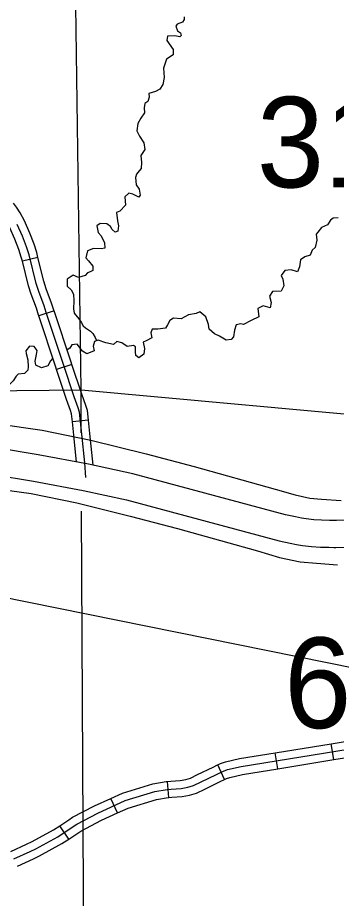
# Model space of a CAD drawing. Extents: x -492261 to -432772, y 1441225 to 1452922.
# Drawn here: x -457961.8 to -457876.9, y 1450967.5 to 1451202.4 of the extents above; entities that cross this region are included whole.
import ezdxf

# ---------------------------------------------------------------- set-up
doc = ezdxf.new("R2010")
doc.units = 0
doc.layers.add('Default', color=7, linetype='Continuous')
doc.layers.add('R_Draft', color=7, linetype='Continuous')

msp = doc.modelspace()

# ---------------------------------------------------------------- linework, layer by layer
at = {"layer": 'Default'}
for p, q in [((-457956.37, 1451138.48), (-457960.53, 1451137.45)), ((-457952.07, 1451124.21), (-457956.14, 1451122.86)), ((-457947.33, 1451109.9), (-457951.4, 1451108.54)), ((-457942.94, 1451095.03), (-457947.2, 1451094.59)), ((-457877.58, 1451004.53), (-457878.26, 1451008.76)), ((-457892.47, 1451002.12), (-457893.15, 1451006.35)), ((-457906.65, 1450999.26), (-457908.46, 1451003.15)), ((-457921.54, 1450994.44), (-457921.87, 1450998.72)), ((-457935.2, 1450990.31), (-457936.98, 1450994.2)), ((-457948.17, 1450983.34), (-457950.54, 1450986.91))]:
    msp.add_line(p, q, dxfattribs=at)
for points in [[(-457944.83, 1451091.7), (-457944.89, 1451103.15), (-457946.83, 1451244.05), (-457946.97, 1451253.15), (-457946.94, 1451394.95), (-457946.87, 1451404.85), (-457947.93, 1451544), (-457948.01, 1451552.92)], [(-457917.4, 1451202.65), (-457917.44, 1451201.93), (-457917.85, 1451201.17), (-457919.27, 1451200.65), (-457919.68, 1451200.12), (-457919.22, 1451198.87), (-457918.38, 1451198.35), (-457918.19, 1451197.61), (-457918.58, 1451197.31), (-457919.9, 1451197.59), (-457921.85, 1451197.49), (-457922.02, 1451196.28), (-457920.38, 1451193.88), (-457920.35, 1451192.48), (-457922.15, 1451191.29), (-457922.89, 1451188.92), (-457922.74, 1451186.48), (-457923.09, 1451184.61), (-457923.95, 1451183.36), (-457925.1, 1451182.7), (-457926.8, 1451182.14), (-457926.78, 1451181.16), (-457927.12, 1451180.04), (-457927.88, 1451179.47), (-457928.08, 1451178.35), (-457928.02, 1451176.98), (-457928.93, 1451175.63), (-457929.75, 1451174.18), (-457930.01, 1451172.22), (-457929.32, 1451170.78), (-457928.16, 1451169), (-457927.94, 1451167.26), (-457928.96, 1451165.66), (-457928.82, 1451163.74), (-457928.87, 1451162.19), (-457929.4, 1451161.52), (-457930.09, 1451160.67), (-457930.35, 1451159.74), (-457930.22, 1451157.82), (-457929.39, 1451156.67), (-457929.18, 1451155.1), (-457929.53, 1451154.54), (-457931.13, 1451155.36), (-457932.13, 1451155.63), (-457933.25, 1451154.62), (-457933.08, 1451152.39), (-457934.56, 1451150.83), (-457935.46, 1451150.41), (-457935.18, 1451148.24), (-457934.94, 1451146.9), (-457935.08, 1451145.49), (-457935.81, 1451145.18), (-457936.63, 1451145.91), (-457937.08, 1451146.67), (-457938.05, 1451147.45), (-457939.76, 1451147.52), (-457940.72, 1451146.87), (-457940.33, 1451145.13), (-457939.51, 1451144.2), (-457938.63, 1451142.33), (-457938.59, 1451140.93), (-457939.56, 1451140.73), (-457941.57, 1451140.8), (-457943.15, 1451140.24), (-457943.65, 1451138.31), (-457942.94, 1451137.55), (-457941.79, 1451136.09), (-457941.76, 1451135), (-457942.47, 1451134.61), (-457943.15, 1451134.33), (-457943.84, 1451133.63), (-457945.57, 1451133.1), (-457946.99, 1451133.72), (-457948.59, 1451132.68), (-457948.6, 1451130.76), (-457947.49, 1451129.84), (-457946.86, 1451128.68), (-457946.82, 1451126.9), (-457946.93, 1451124.78), (-457946.7, 1451123.61), (-457945.47, 1451122.12), (-457944.84, 1451121.22), (-457944.33, 1451120.25), (-457943.69, 1451119.7), (-457942.38, 1451118.81), (-457941.79, 1451118.14), (-457941.16, 1451117.06), (-457941.04, 1451116.84), (-457940.65, 1451116.24)], [(-457956.37, 1451138.48), (-457956.68, 1451139.73), (-457957.41, 1451141.97), (-457958.55, 1451144.91), (-457959.96, 1451148.19), (-457961.07, 1451150.34), (-457962.07, 1451151.89), (-457962.93, 1451152.97)], [(-457960.53, 1451137.45), (-457960.8, 1451138.55), (-457961.45, 1451140.53), (-457962.52, 1451143.29), (-457963.84, 1451146.36), (-457964.78, 1451148.19), (-457965.55, 1451149.38), (-457966.28, 1451150.29)], [(-457877.77, 1451148.92), (-457878.47, 1451148.41), (-457879.27, 1451147.13), (-457880.85, 1451146.4), (-457881.85, 1451145.18), (-457882.24, 1451144.68), (-457882.11, 1451143.08), (-457882.55, 1451141.09), (-457883.33, 1451140.35), (-457883.87, 1451139.05), (-457885.29, 1451138.61), (-457886.41, 1451137.78), (-457886.73, 1451135.96), (-457887.27, 1451134.63), (-457888.95, 1451135.19), (-457890.63, 1451134.95), (-457891.6, 1451133.66), (-457891.14, 1451132.67), (-457890.9, 1451130.9), (-457891.6, 1451129.42), (-457893.86, 1451129.34), (-457894.66, 1451128.17), (-457894.27, 1451126.4), (-457894.52, 1451125.05), (-457896.36, 1451125.52), (-457897.78, 1451124.88), (-457897.58, 1451122.59), (-457899.58, 1451121.62), (-457901.61, 1451120.57), (-457902.36, 1451120.72), (-457903.56, 1451120.49), (-457903.98, 1451119.02), (-457904.28, 1451117.32), (-457904.92, 1451116.59), (-457906.28, 1451116.35), (-457908, 1451117.49), (-457909.36, 1451118.08), (-457910.76, 1451119.31), (-457910.97, 1451120.57), (-457911.62, 1451122.59), (-457913.25, 1451123.95), (-457914.27, 1451123.49), (-457916.24, 1451123.13), (-457917.22, 1451122.62), (-457918.18, 1451122.08), (-457920.24, 1451122.23), (-457921.26, 1451121.63), (-457921.83, 1451120.5), (-457922.38, 1451119.57), (-457924.43, 1451119.29), (-457925.95, 1451119.33), (-457926.27, 1451118.32), (-457926.06, 1451117.04), (-457927.56, 1451116.2), (-457928.38, 1451115.89), (-457927.99, 1451114.15), (-457928.18, 1451112.65), (-457929.5, 1451111.68), (-457930.32, 1451112.31), (-457930.37, 1451113.32), (-457930.35, 1451114.64), (-457930.9, 1451114.94), (-457932.58, 1451114.7), (-457934.03, 1451115.72), (-457935.33, 1451116), (-457936.25, 1451115.26), (-457938.27, 1451115.67), (-457940.31, 1451116.37), (-457941.31, 1451116), (-457941.67, 1451114.76), (-457941.44, 1451113.53), (-457943.34, 1451112.79), (-457944.53, 1451113.48), (-457945.95, 1451115.31), (-457947.38, 1451115.15), (-457947.87, 1451114.23), (-457948.62, 1451113.8)], [(-457876.37, 1451149.04), (-457877.77, 1451148.92)], [(-457943.58, 1451079.8), (-457943.89, 1451083.65), (-457944.71, 1451091.31), (-457945.32, 1451097.17), (-457945.66, 1451098.31), (-457946.71, 1451101.27), (-457949.59, 1451109.89), (-457954.17, 1451123.74), (-457954.76, 1451125.59), (-457956.17, 1451129.39), (-457956.86, 1451131.5), (-457958.74, 1451139.14), (-457959.43, 1451141.25), (-457960.53, 1451144.1), (-457961.9, 1451147.27)], [(-457956.14, 1451122.86), (-457956.21, 1451123.07), (-457956.79, 1451124.89), (-457958.2, 1451128.69), (-457958.92, 1451130.91), (-457960.53, 1451137.45)], [(-457952.07, 1451124.21), (-457952.13, 1451124.4), (-457952.74, 1451126.29), (-457954.15, 1451130.1), (-457954.8, 1451132.09), (-457956.37, 1451138.48)], [(-457951.4, 1451108.54), (-457951.62, 1451109.21), (-457956.14, 1451122.86)], [(-457947.33, 1451109.9), (-457947.55, 1451110.56), (-457952.07, 1451124.21)], [(-457952.42, 1451111.63), (-457953.01, 1451110.91), (-457953.75, 1451109.51), (-457955.42, 1451109.04), (-457956.93, 1451109.69), (-457957.1, 1451110.77), (-457956.77, 1451112.53), (-457956.6, 1451113.62), (-457957.34, 1451114.72), (-457958.66, 1451114.78), (-457959.6, 1451113.55), (-457959.52, 1451112.81), (-457959.05, 1451111.18), (-457958.95, 1451109.32), (-457959.07, 1451108.43), (-457959.99, 1451107.52), (-457961.67, 1451107.3), (-457962.14, 1451106.83), (-457963, 1451105.58), (-457964.19, 1451104.29), (-457965.6, 1451103.72)], [(-457947.2, 1451094.59), (-457947.43, 1451096.75), (-457947.7, 1451097.65), (-457948.73, 1451100.57), (-457951.4, 1451108.54)], [(-457942.94, 1451095.03), (-457943.21, 1451097.6), (-457943.62, 1451098.98), (-457944.68, 1451101.97), (-457947.33, 1451109.9)], [(-458133.38, 1451104.9), (-458115.55, 1451104.19), (-458090.28, 1451102.44), (-458073, 1451100.71), (-458059.92, 1451099.9), (-458047.02, 1451099.12), (-458037.42, 1451098.53), (-458025.35, 1451097.79), (-458010.61, 1451096.61), (-457997.23, 1451096.3), (-457978.53, 1451095.19), (-457967.08, 1451094.07), (-457955.21, 1451092.35), (-457942.26, 1451089.71), (-457927.54, 1451086.04), (-457914.76, 1451082.72), (-457893.22, 1451076.66), (-457887.87, 1451075.11), (-457883.92, 1451074.26), (-457880.8, 1451073.98), (-457875.64, 1451073.62)], [(-458013.42, 1451102.45), (-457944.89, 1451103.15)], [(-457944.89, 1451103.15), (-457819.38, 1451091.68), (-457674.19, 1451084.35), (-457670.22, 1451084.1)], [(-457946.07, 1451083.89), (-457946.84, 1451091.09), (-457947.2, 1451094.59)], [(-457941.66, 1451083.04), (-457942.58, 1451091.54), (-457942.94, 1451095.03)], [(-457843.02, 1451068.36), (-457853.33, 1451068.39), (-457876.89, 1451068.26), (-457877.34, 1451068.28), (-457878.72, 1451068.3), (-457880.8, 1451068.36), (-457882.91, 1451068.48), (-457884.91, 1451068.71), (-457886.21, 1451068.93), (-457887.75, 1451069.25), (-457890.42, 1451069.82), (-457931.07, 1451080.76), (-457942.94, 1451083.31), (-457956.3, 1451085.79), (-457967.48, 1451087.69), (-458017.21, 1451091.66), (-458018.99, 1451091.77)], [(-458134.05, 1451087.77), (-458116.48, 1451087.07), (-458091.73, 1451085.36), (-458074.39, 1451083.62), (-458060.97, 1451082.79), (-458048.06, 1451082.01), (-458038.48, 1451081.42), (-458026.56, 1451080.69), (-458011.49, 1451079.48), (-457997.94, 1451079.17), (-457979.87, 1451078.1), (-457969.15, 1451077.05), (-457958.15, 1451075.46), (-457946.04, 1451072.99), (-457931.78, 1451069.43), (-457919.24, 1451066.17), (-457897.93, 1451060.18), (-457892.05, 1451058.47), (-457886.5, 1451057.29), (-457882.19, 1451056.89), (-457876.61, 1451056.5)], [(-458019.43, 1451084.64), (-458017.72, 1451084.54), (-457968.36, 1451080.59), (-457957.55, 1451078.76), (-457944.35, 1451076.31), (-457932.75, 1451073.82), (-457892.09, 1451062.87), (-457889.21, 1451062.26), (-457887.54, 1451061.92), (-457885.93, 1451061.64), (-457883.52, 1451061.36), (-457881.1, 1451061.22), (-457878.88, 1451061.16), (-457877.52, 1451061.14), (-457876.99, 1451061.12), (-457853.32, 1451061.25), (-457843.04, 1451061.22)], [(-457945.49, 1450741.98), (-457945.04, 1450799.46), (-457944.16, 1450953.01), (-457944.73, 1451070.81)], [(-457878.26, 1451008.76), (-457870.77, 1451009.97), (-457867, 1451010.35), (-457863.15, 1451010.49), (-457862.92, 1451010.48)], [(-457962.76, 1450978.06), (-457958.46, 1450980.03), (-457956.97, 1450980.75), (-457951.1, 1450983.97), (-457946.96, 1450986.71), (-457946.06, 1450987.3), (-457940.39, 1450990.28), (-457933.13, 1450993.62), (-457925.27, 1450995.99), (-457921.94, 1450996.56), (-457920.85, 1450996.65), (-457918.25, 1450996.8), (-457916.49, 1450997.16), (-457914.93, 1450997.62), (-457912.89, 1450998.62), (-457908.8, 1451000.59), (-457907.58, 1451001.19), (-457906.93, 1451001.49), (-457905.86, 1451001.86), (-457902.27, 1451002.7), (-457870.49, 1451007.85)], [(-457893.15, 1451006.35), (-457878.26, 1451008.76)], [(-457908.46, 1451003.15), (-457907.74, 1451003.48), (-457906.45, 1451003.93), (-457902.69, 1451004.8), (-457893.15, 1451006.35)], [(-457877.58, 1451004.53), (-457870.21, 1451005.72), (-457866.71, 1451006.08), (-457863.11, 1451006.2), (-457862.98, 1451006.2)], [(-457921.87, 1450998.72), (-457921, 1450998.78), (-457918.53, 1450998.93), (-457917.01, 1450999.24), (-457915.71, 1450999.63), (-457913.83, 1451000.55), (-457909.74, 1451002.51), (-457908.51, 1451003.12), (-457908.46, 1451003.15)], [(-457892.47, 1451002.12), (-457877.58, 1451004.53)], [(-457906.65, 1450999.26), (-457906.13, 1450999.5), (-457905.26, 1450999.8), (-457901.86, 1451000.59), (-457892.47, 1451002.12)], [(-457936.98, 1450994.2), (-457933.89, 1450995.63), (-457925.76, 1450998.08), (-457922.2, 1450998.69), (-457921.87, 1450998.72)], [(-457921.54, 1450994.44), (-457920.71, 1450994.51), (-457917.98, 1450994.67), (-457915.97, 1450995.08), (-457914.14, 1450995.62), (-457911.96, 1450996.69), (-457907.86, 1450998.66), (-457906.65, 1450999.26), (-457906.65, 1450999.26)], [(-457950.54, 1450986.91), (-457948.15, 1450988.49), (-457947.16, 1450989.15), (-457941.34, 1450992.21), (-457936.98, 1450994.2)], [(-457935.2, 1450990.31), (-457932.37, 1450991.61), (-457924.77, 1450993.9), (-457921.67, 1450994.43), (-457921.54, 1450994.44)], [(-457948.17, 1450983.34), (-457945.78, 1450984.92), (-457944.97, 1450985.46), (-457939.45, 1450988.36), (-457935.2, 1450990.31)], [(-457963.57, 1450980.04), (-457959.38, 1450981.96), (-457957.95, 1450982.66), (-457952.21, 1450985.8), (-457950.54, 1450986.91)], [(-457961.78, 1450976.15), (-457957.55, 1450978.09), (-457955.98, 1450978.85), (-457949.99, 1450982.13), (-457948.17, 1450983.34)]]:
    msp.add_lwpolyline(points, dxfattribs=at)
at = {"layer": 'R_Draft'}
msp.add_line((-458231.04, 1451101.7), (-457691.3, 1450992.37), dxfattribs=at)

# ---------------------------------------------------------------- texts
at = {"layer": 'Default'}
for s, height, p in [('31', 24.137, (-457898.08, 1451157.14)), ('6', 24.14, (-457890.8, 1451012.95))]:
    msp.add_text(s, height=height, dxfattribs=at).set_placement(p)

doc.saveas('drawing.dxf')
